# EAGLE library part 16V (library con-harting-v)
CONNECTOR
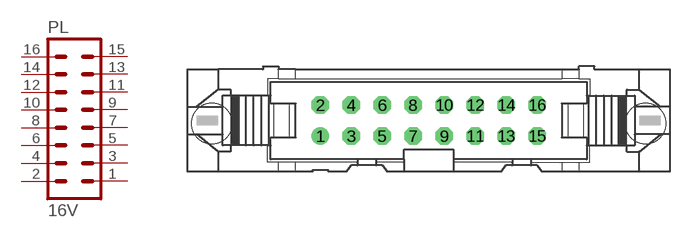
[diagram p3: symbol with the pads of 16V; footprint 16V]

Designator prefix PL

## 16V (OC_FARNELL: unknown; OC_NEWARK: unknown)  [16V]
1  1  pas
2  2  pas
3  3  pas
4  4  pas
5  5  pas
6  6  pas
7  7  pas
8  8  pas
9  9  pas
10  10  pas
11  11  pas
12  12  pas
13  13  pas
14  14  pas
15  15  pas
16  16  pas

## Footprint 16V (pad centres in mm)
CONNECTOR
drill 0.914 round: 1 -8.89,-1.27
drill 0.914 octagon: 2 -8.89,1.27; 3 -6.35,-1.27; 4 -6.35,1.27; 5 -3.81,-1.27; 6 -3.81,1.27; 7 -1.27,-1.27; 8 -1.27,1.27; 9 1.27,-1.27; 10 1.27,1.27; 11 3.81,-1.27; 12 3.81,1.27; 13 6.35,-1.27; 14 6.35,1.27; 15 8.89,-1.27; 16 8.89,1.27
hole 3.302 at 17.78,-0.254
hole 3.302 at -17.78,-0.254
